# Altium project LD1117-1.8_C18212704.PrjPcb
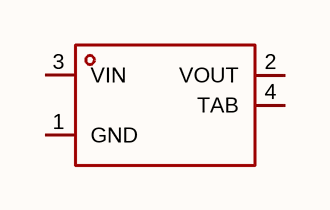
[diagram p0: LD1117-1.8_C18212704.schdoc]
1 sheet, 1 parts. Net scope: global (net labels, ports and power ports of the same name join across sheets).

## Sheet LD1117-1.8_C18212704.schdoc
size 127 x 101 mm

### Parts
U?  ld1117-1.8_c18212704  [SOT-223-3_L6.5-W3.4-P2.30-LS7.0-BR]  (value not drawn)

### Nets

Not connected (* = marked no-connect by the designer): U? 1(GND) 2(VOUT) 3(VIN) 4(TAB)

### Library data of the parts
U? = ld1117-1.8_c18212704: 输出极性:正极;工作电压:12V;输出电压:1.8V;输出电流:1A;电源纹波抑制比(PSRR):-;输出类型:固定;; Manufacturer: TECH PUBLIC(台舟); AddInBom: yes; ModelId: 925194bf9823436183a3e0b978a8d076; ModelName: SOT-223-4P_L6.5-W3.5-H1.6-LS7.0-P2.30; ModelTransform: 279.89794,255.905,0,180,0,0,-3.9385,-0.0005,0; Output Configuration: 正极; Voltage - Supply: 12V; Output Voltage: 1.8V; Output Current: 1A; standby current: 4mA; Output Type: 固定; Number of Outputs: 1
